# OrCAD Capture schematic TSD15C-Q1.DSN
size A; title: TSDxxC-Q1 Bidrectional TVS Diodes in SOD-323 Package; rev: 1.0; note: Datasheet: SLVSHX0
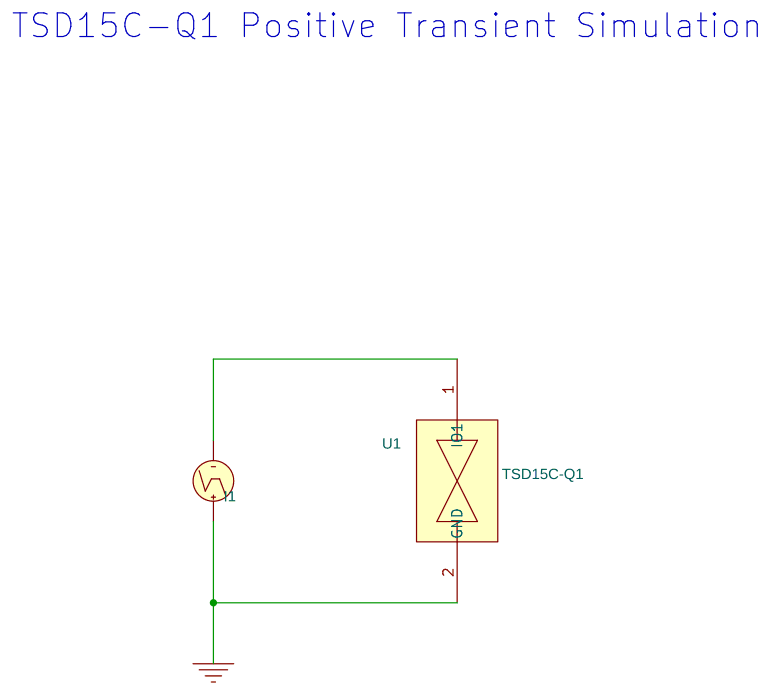
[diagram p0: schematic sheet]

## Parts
I1  IPWL_GENERIC
U1  TSD15C-Q1

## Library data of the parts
I1 = IPWL_GENERIC: AppProp: No_reps$POINTS_TYPE_PWL$0$0; FIRST_NPAIRS: 0n 0 0.8n 30 6n 8 9.5n 12.5 10n 13 18n 16 22n 16 25n 16 60n 9 72n 7 82n 5.3 150n 0; PSpiceTemplate: I^@REFDES %+ %- ?DC|DC @DC| ?AC|AC @AC| PWL ?TSF|TIME_SCALE_FACTOR=@TSF| ?VSF|VALUE_SCALE_FACTOR=@VSF| ?REPEAT_VALUE| \n+ REPEAT FOR @REPEAT_VALUE| \n+ @FIRST_NPAIRS ?SECOND_NPAIRS|\n+ @SECOND_NPAIRS ?THIRD_NPAIRS/\n+ @THIRD_NPAIRS/| ?REPEAT_VALUE| \n+ ENDREPEAT|
U1 = TSD15C-Q1

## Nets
0: I1.1(+) U1.2(GND)
N02959: I1.2(-) U1.1(IO1)

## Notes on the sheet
- TSD15C-Q1 Positive Transient Simulation
